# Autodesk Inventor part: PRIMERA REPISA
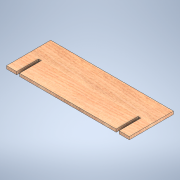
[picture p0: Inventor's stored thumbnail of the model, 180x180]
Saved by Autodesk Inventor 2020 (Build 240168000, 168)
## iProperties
Created: 2020-03
Part Number: PRIMERA REPISA
Material: Madera (abedul)
Document SubType Name: Modeling
Designer: Arias
Density: 0.55 g/cm^3
Appearance: Abedul - Natural pulido
Author: Arias
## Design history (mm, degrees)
sketch "Boceto1"
  geometry: L1 (0, 0)-(480, 0); L2 (480, 0)-(480, -172.526); L3 (480, -172.526)-(0, -172.526); L4 (0, -172.526)-(0, 0); L5 (440, 0)-(440, -85); L6 (51.1, 0)-(51.1, -85); L7 (428.9, 0)-(428.9, -85); L8 (40, 0)-(40, -85); L9 (440, -85)-(428.9, -85); L10 (51.1, -85)-(40, -85); 2 further points
  constraints: 20 end point, 5 equal length, 2 perpendicular, 2 point on line, 2 vertical, 1 horizontal
  dimensions: "d0" = 480 distance of L2.end L3.end; "d1" = 172.526 distance of L1.end L2.end; "d2" = 85 distance of L5.start L5.end; "d3" = 85 distance of L6.start L6.end; "d4" = 11.1 distance between parallel lines of L5 L7; "d5" = 11.1 distance between parallel lines of L6 L8; "d6" = 400 distance between parallel lines of L8 L5; "d7" = 40 distance between parallel lines of L4 L8
extrude "Extrusión1" new body sketch "Boceto1" distance "d8" = 11.1; taper "d9" = 0 deg
node "Sólido1"
